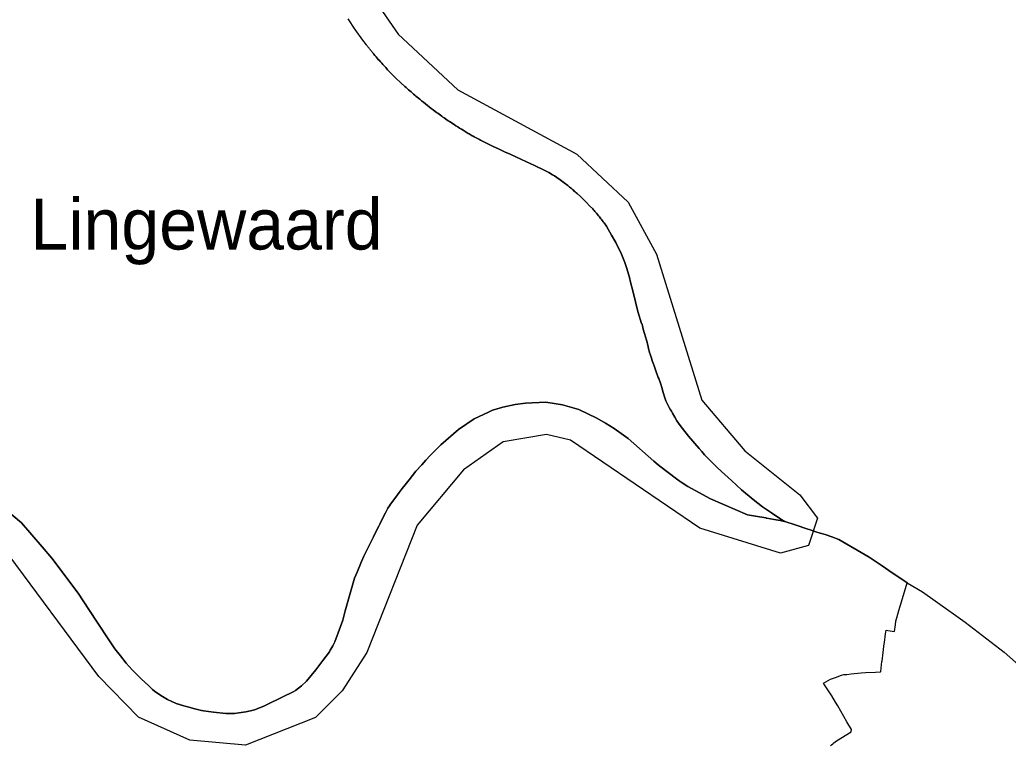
# Model space of a CAD drawing. Extents: x 113371 to 291721, y 393993 to 520143.
# Drawn here: x 192843 to 202548, y 429408 to 436525 of the extents above; entities that cross this region are included whole.
import ezdxf

# ---------------------------------------------------------------- set-up
doc = ezdxf.new("R2010")
doc.units = 0
for name, color, linetype in [('Boudingbox', 7, 'Continuous'), ('Default', 7, 'Continuous'), ('plaatsnamen', 7, 'Continuous'), ('vlieg gebied', 7, 'Continuous')]:
    doc.layers.add(name, color=color, linetype=linetype)

msp = doc.modelspace()

# ---------------------------------------------------------------- linework, layer by layer
at = {"layer": 'Boudingbox'}
msp.add_lwpolyline([(195676.083719, 437658.225888), (196556.945896, 436383.18747), (197142.997241, 435836.21838), (198310.654147, 435206.744651), (198814.741867, 434734.213382), (199092.660318, 434225.807727), (199540.546097, 432791.333676), (199962.119297, 432294.46026), (200501.752782, 431862.805644), (200676.148243, 431636.761083), (200585.491717, 431366.037395), (200310.139354, 431290.598699), (199520.441064, 431535.6128), (198250.155432, 432401.539517), (198015.469874, 432454.9006), (197590.459702, 432383.583408), (197198.077187, 432108.605271), (196744.145674, 431566.525607), (196251.335617, 430318.065969), (196009.740202, 429942.724312), (195746.220423, 429678.545334), (195058.112665, 429409.591246), (194512.13961, 429456.44294), (194007.836888, 429681.796786), (193619.497196, 430081.251608), (192673.95631, 431358.421884)], dxfattribs=at)
at = {"layer": 'Default'}
for points in [[(196426.065625, 436065.8025), (196416.625625, 436076.2125), (196407.225625, 436086.6725), (196396.055625, 436099.0625), (196384.925625, 436111.5125), (196373.855625, 436124.0025), (196362.845625, 436136.5325), (196351.875625, 436149.1225), (196342.455625, 436160.0125), (196340.965625, 436161.7425), (196330.095625, 436174.4125), (196319.285625, 436187.1325), (196314.195625, 436193.1725), (196311.805625, 436195.9325), (196308.695625, 436199.5325), (196303.245625, 436205.9325), (196297.855625, 436212.3925), (196292.525625, 436218.8925), (196287.255625, 436225.4425), (196282.035625, 436232.0325), (196276.885625, 436238.6725), (196271.785625, 436245.3625), (196266.745625, 436252.0925), (196261.765625, 436258.8625), (196256.845625, 436265.6825), (196251.985625, 436272.5425), (196247.175625, 436279.4425), (196212.255625, 436324.4525), (196136.355625, 436430.4725), (196067.825625, 436535.0125)], [(196310.250625, 436197.7325), (196311.805625, 436195.9325), (196314.195625, 436193.1725), (196319.285625, 436187.1325), (196330.095625, 436174.4125), (196340.965625, 436161.7425), (196342.455625, 436160.0125), (196351.875625, 436149.1225), (196362.845625, 436136.5325), (196373.855625, 436124.0025), (196384.925625, 436111.5125), (196396.055625, 436099.0625), (196407.225625, 436086.6725), (196416.625625, 436076.2125), (196426.065625, 436065.8025), (196435.565625, 436055.4425), (196445.115625, 436045.1325), (196454.725625, 436034.8625), (196464.385625, 436024.6525), (196474.095625, 436014.4825), (196483.855625, 436004.3725), (196493.665625, 435994.3025), (196503.535625, 435984.2925), (196513.445625, 435974.3225), (196535.915625, 435951.9225), (196584.575625, 435906.3825), (196624.255625, 435870.0525), (196636.105625, 435859.3525), (196648.015625, 435848.7025), (196659.965625, 435838.1125), (196671.955625, 435827.5725), (196683.995625, 435817.0825), (196696.085625, 435806.6525), (196708.225625, 435796.2725), (196720.405625, 435785.9525), (196732.635625, 435775.6825), (196744.905625, 435765.4725)], [(196985.115625, 435579.5425), (196972.175625, 435588.7325), (196959.285625, 435597.9725), (196946.435625, 435607.2725), (196933.625625, 435616.6325), (196920.865625, 435626.0425), (196901.805625, 435640.7425), (196882.785625, 435655.5025), (196863.805625, 435670.3125), (196844.875625, 435685.1825), (196825.995625, 435700.1025), (196807.145625, 435715.0825), (196788.345625, 435730.1125), (196769.595625, 435745.2025), (196757.225625, 435755.3125), (196744.905625, 435765.4725), (196732.635625, 435775.6825), (196720.405625, 435785.9525), (196708.225625, 435796.2725), (196696.085625, 435806.6525), (196683.995625, 435817.0825), (196671.955625, 435827.5725), (196659.965625, 435838.1125), (196648.015625, 435848.7025), (196636.105625, 435859.3525), (196624.255625, 435870.0525), (196584.575625, 435906.3825), (196535.915625, 435951.9225), (196513.445625, 435974.3225), (196503.535625, 435984.2925), (196493.665625, 435994.3025), (196483.855625, 436004.3725), (196474.095625, 436014.4825), (196464.385625, 436024.6525), (196454.725625, 436034.8625), (196445.115625, 436045.1325), (196435.565625, 436055.4425), (196426.065625, 436065.8025)], [(196744.905625, 435765.4725), (196757.225625, 435755.3125), (196769.595625, 435745.2025), (196788.345625, 435730.1125), (196807.145625, 435715.0825), (196825.995625, 435700.1025), (196844.875625, 435685.1825), (196863.805625, 435670.3125), (196882.785625, 435655.5025), (196901.805625, 435640.7425), (196920.865625, 435626.0425), (196933.625625, 435616.6325), (196946.435625, 435607.2725), (196959.285625, 435597.9725), (196972.175625, 435588.7325), (196985.115625, 435579.5425), (196998.085625, 435570.4125), (197011.095625, 435561.3425), (197024.155625, 435552.3325), (197037.245625, 435543.3825), (197050.375625, 435534.4825), (197063.555625, 435525.6425), (197076.765625, 435516.8625), (197090.015625, 435508.1425), (197107.645625, 435496.7625), (197125.305625, 435485.4325), (197143.005625, 435474.1625), (197160.735625, 435462.9325), (197178.505625, 435451.7725), (197196.305625, 435440.6525), (197205.985625, 435434.4725), (197215.695625, 435428.3625), (197225.445625, 435422.3025), (197235.235625, 435416.3125), (197245.065625, 435410.3825), (197254.935625, 435404.5125), (197264.835625, 435398.7125), (197274.775625, 435392.9725)], [(197542.795625, 435258.5125), (197491.265625, 435282.2325), (197431.245625, 435310.7425), (197418.465625, 435317.0025), (197405.715625, 435323.3225), (197392.985625, 435329.7125), (197380.295625, 435336.1625), (197367.635625, 435342.6625), (197355.005625, 435349.2325), (197342.415625, 435355.8725), (197329.845625, 435362.5625), (197317.315625, 435369.3125), (197304.815625, 435376.1325), (197294.765625, 435381.6725), (197284.755625, 435387.2925), (197274.775625, 435392.9725), (197264.835625, 435398.7125), (197254.935625, 435404.5125), (197245.065625, 435410.3825), (197235.235625, 435416.3125), (197225.445625, 435422.3025), (197215.695625, 435428.3625), (197205.985625, 435434.4725), (197196.305625, 435440.6525), (197178.505625, 435451.7725), (197160.735625, 435462.9325), (197143.005625, 435474.1625), (197125.305625, 435485.4325), (197107.645625, 435496.7625), (197090.015625, 435508.1425), (197076.765625, 435516.8625), (197063.555625, 435525.6425), (197050.375625, 435534.4825), (197037.245625, 435543.3825), (197024.155625, 435552.3325), (197011.095625, 435561.3425), (196998.085625, 435570.4125), (196985.115625, 435579.5425)], [(197274.775625, 435392.9725), (197284.755625, 435387.2925), (197294.765625, 435381.6725), (197304.815625, 435376.1325), (197317.315625, 435369.3125), (197329.845625, 435362.5625), (197342.415625, 435355.8725), (197355.005625, 435349.2325), (197367.635625, 435342.6625), (197380.295625, 435336.1625), (197392.985625, 435329.7125), (197405.715625, 435323.3225), (197418.465625, 435317.0025), (197431.245625, 435310.7425), (197491.265625, 435282.2325), (197542.795625, 435258.5125), (197603.035625, 435230.8625), (197656.285625, 435206.4325), (197769.925625, 435154.6425), (197895.025625, 435096.4125), (197997.345625, 435046.0025), (198036.205625, 435025.4625), (198071.645625, 435005.2225), (198091.895625, 434992.6425), (198116.605625, 434976.1725), (198148.315625, 434954.3125), (198187.315625, 434925.7225), (198222.735625, 434898.4925), (198240.785625, 434883.6625), (198258.755625, 434868.7225), (198268.355625, 434860.7125), (198277.915625, 434852.6425), (198287.415625, 434844.5125), (198296.865625, 434836.3125), (198306.255625, 434828.0625), (198315.605625, 434819.7525), (198347.735625, 434789.6225), (198378.535625, 434760.3225)], [(198556.565625, 434562.0625), (198548.915625, 434572.0925), (198541.215625, 434582.0825), (198533.455625, 434592.0225), (198525.635625, 434601.9125), (198518.585625, 434610.4225), (198511.485625, 434618.8825), (198504.335625, 434627.2925), (198497.125625, 434635.6625), (198489.865625, 434643.9925), (198482.555625, 434652.2725), (198475.195625, 434660.5125), (198467.785625, 434668.7025), (198437.875625, 434699.8425), (198407.985625, 434731.0225), (198378.535625, 434760.3225), (198347.735625, 434789.6225), (198315.605625, 434819.7525), (198306.255625, 434828.0625), (198296.865625, 434836.3125), (198287.415625, 434844.5125), (198277.915625, 434852.6425), (198268.355625, 434860.7125), (198258.755625, 434868.7225), (198240.785625, 434883.6625), (198222.735625, 434898.4925), (198187.315625, 434925.7225), (198148.315625, 434954.3125), (198116.605625, 434976.1725), (198091.895625, 434992.6425), (198071.645625, 435005.2225), (198036.205625, 435025.4625), (197997.345625, 435046.0025), (197895.025625, 435096.4125), (197769.925625, 435154.6425), (197656.285625, 435206.4325), (197603.035625, 435230.8625), (197542.795625, 435258.5125)], [(198378.535625, 434760.3225), (198407.985625, 434731.0225), (198437.875625, 434699.8425), (198467.785625, 434668.7025), (198475.195625, 434660.5125), (198482.555625, 434652.2725), (198489.865625, 434643.9925), (198497.125625, 434635.6625), (198504.335625, 434627.2925), (198511.485625, 434618.8825), (198518.585625, 434610.4225), (198525.635625, 434601.9125), (198533.455625, 434592.0225), (198541.215625, 434582.0825), (198548.915625, 434572.0925), (198556.565625, 434562.0625), (198564.155625, 434551.9925), (198571.685625, 434541.8825), (198579.155625, 434531.7225), (198602.045625, 434499.0225), (198622.665625, 434464.9325), (198636.925625, 434439.5025), (198653.615625, 434410.0625), (198693.805625, 434339.4625), (198750.605625, 434226.3925), (198784.135625, 434142.8025), (198802.545625, 434083.9025), (198829.065625, 433995.3025), (198840.145625, 433950.8625), (198860.555625, 433866.0325), (198886.745625, 433757.6525), (198910.025625, 433662.6925), (198948.535625, 433546.2725), (198948.755625, 433545.5825), (198951.965625, 433534.0825), (198955.945625, 433522.1525), (198962.895625, 433490.3625), (198976.805625, 433445.6625)], [(199084.605625, 433090.7625), (199071.015625, 433130.4325), (199061.465625, 433156.8825), (199053.305625, 433178.9925), (199047.425625, 433195.5225), (199040.815625, 433213.8925), (199034.575625, 433235.5625), (199026.855625, 433262.0125), (199022.445625, 433277.0725), (199020.535625, 433284.8625), (199013.565625, 433316.0825), (199008.785625, 433331.8825), (199006.585625, 433342.5325), (199001.435625, 433361.2725), (198996.675625, 433381.0925), (198976.805625, 433445.6625), (198962.895625, 433490.3625), (198955.945625, 433522.1525), (198951.965625, 433534.0825), (198948.755625, 433545.5825), (198948.535625, 433546.2725), (198910.025625, 433662.6925), (198886.745625, 433757.6525), (198860.555625, 433866.0325), (198840.145625, 433950.8625), (198829.065625, 433995.3025), (198802.545625, 434083.9025), (198784.135625, 434142.8025), (198750.605625, 434226.3925), (198693.805625, 434339.4625), (198653.615625, 434410.0625), (198636.925625, 434439.5025), (198622.665625, 434464.9325), (198602.045625, 434499.0225), (198579.155625, 434531.7225), (198571.685625, 434541.8825), (198564.155625, 434551.9925), (198556.565625, 434562.0625)], [(198976.805625, 433445.6625), (198996.675625, 433381.0925), (199001.435625, 433361.2725), (199006.585625, 433342.5325), (199008.785625, 433331.8825), (199013.565625, 433316.0825), (199020.535625, 433284.8625), (199022.445625, 433277.0725), (199026.855625, 433262.0125), (199034.575625, 433235.5625), (199040.815625, 433213.8925), (199047.425625, 433195.5225), (199053.305625, 433178.9925), (199061.465625, 433156.8825), (199071.015625, 433130.4325), (199084.605625, 433090.7625), (199112.155625, 433014.7225), (199115.905625, 433003.9925), (199138.305625, 432951.0925), (199147.195625, 432916.4925), (199160.055625, 432868.0025), (199177.105625, 432814.9625), (199186.655625, 432787.7725), (199194.735625, 432767.9425), (199202.815625, 432753.2425), (199219.715625, 432721.6525), (199232.205625, 432699.6125), (199241.015625, 432684.9225), (199252.035625, 432664.3525), (199274.075625, 432625.4125), (199295.385625, 432590.8825), (199327.635625, 432543.0925), (199349.335625, 432515.2725), (199408.585625, 432439.2925), (199513.835625, 432320.1125), (199537.875625, 432290.6725), (199564.285625, 432257.7525), (199575.425625, 432246.6225)], [(200362.955625, 431598.0725), (200364.035625, 431597.7425), (200364.625625, 431597.5625), (200315.665625, 431626.9325), (200224.285625, 431687.7525), (200134.285625, 431747.7525), (200044.285625, 431817.7525), (199928.455625, 431914.7625), (199829.525625, 432005.1825), (199731.385625, 432093.1125), (199688.095625, 432135.4125), (199670.175625, 432152.9225), (199657.685625, 432165.1325), (199624.285625, 432197.7525), (199594.755625, 432227.2925), (199575.425625, 432246.6225), (199564.285625, 432257.7525), (199537.875625, 432290.6725), (199513.835625, 432320.1125), (199408.585625, 432439.2925), (199349.335625, 432515.2725), (199327.635625, 432543.0925), (199295.385625, 432590.8825), (199274.075625, 432625.4125), (199252.035625, 432664.3525), (199241.015625, 432684.9225), (199232.205625, 432699.6125), (199219.715625, 432721.6525), (199202.815625, 432753.2425), (199194.735625, 432767.9425), (199186.655625, 432787.7725), (199177.105625, 432814.9625), (199160.055625, 432868.0025), (199147.195625, 432916.4925), (199138.305625, 432951.0925), (199115.905625, 433003.9925), (199112.155625, 433014.7225), (199084.605625, 433090.7625)], [(199625.165625, 431823.8925), (199402.485625, 431944.3425), (199337.425625, 431987.7925), (199316.065625, 432002.5025), (199181.195625, 432101.6225), (199111.895625, 432157.8825), (199068.725625, 432192.9325), (198814.545625, 432416.9725), (198679.375625, 432515.0725), (198592.715625, 432567.4725), (198509.035625, 432615.7025), (198332.335625, 432700.2425), (198171.945625, 432747.5925), (198006.335625, 432773.7625), (197806.515625, 432764.4125), (197706.135625, 432750.8025), (197584.515625, 432724.1025), (197497.525625, 432698.1925), (197485.725625, 432693.3125), (197443.855625, 432675.9825), (197303.195625, 432610.2825), (197149.575625, 432506.6325), (196976.905625, 432354.9125), (196959.475625, 432337.7625), (196927.095625, 432304.3925), (196876.155625, 432253.1225), (196828.935625, 432204.7525), (196789.385625, 432159.1225), (196732.915625, 432095.1425), (196664.765625, 432011.9125), (196652.635625, 431996.3625), (196625.645625, 431961.2025), (196597.585625, 431925.3825), (196568.145625, 431886.9025), (196550.365625, 431862.5125), (196515.395625, 431815.5725), (196483.395625, 431771.9125), (196472.605625, 431757.2025)], [(196876.155625, 432253.1225), (196927.095625, 432304.3925), (196959.475625, 432337.7625), (196976.905625, 432354.9125), (197149.575625, 432506.6325), (197303.195625, 432610.2825), (197443.855625, 432675.9825), (197485.725625, 432693.3125), (197497.525625, 432698.1925), (197584.515625, 432724.1025), (197706.135625, 432750.8025), (197806.515625, 432764.4125), (198006.335625, 432773.7625), (198171.945625, 432747.5925), (198332.335625, 432700.2425), (198509.035625, 432615.7025), (198592.715625, 432567.4725), (198679.375625, 432515.0725), (198814.545625, 432416.9725), (199068.725625, 432192.9325), (199111.895625, 432157.8825), (199181.195625, 432101.6225), (199316.065625, 432002.5025), (199337.425625, 431987.7925), (199402.485625, 431944.3425), (199625.165625, 431823.8925), (199746.425625, 431772.2425), (199987.065625, 431666.4425), (200046.945625, 431657.3125), (200087.395625, 431650.5025), (200148.075625, 431640.2825), (200166.975625, 431637.1025), (200169.875625, 431636.5825), (200170.115625, 431636.5425), (200178.375625, 431635.0725), (200248.155625, 431622.6925), (200308.385625, 431610.9125), (200362.955625, 431598.0725)], [(195817.425625, 430237.8025), (195883.065625, 430324.8525), (195890.975625, 430338.9325), (195897.425625, 430350.4025), (195915.305625, 430382.8725), (195934.995625, 430421.4225), (195936.355625, 430424.4225), (195947.195625, 430448.2525), (196013.705625, 430635.8025), (196038.775625, 430726.3625), (196129.135625, 431045.7225), (196155.935625, 431105.0725), (196191.945625, 431194.9525), (196198.815625, 431210.4225), (196222.125625, 431262.9025), (196247.685625, 431314.8625), (196270.775625, 431361.8625), (196293.865625, 431407.2225), (196315.305625, 431452.5725), (196336.755625, 431492.9825), (196368.085625, 431556.4825), (196377.155625, 431575.4525), (196405.195625, 431632.3525), (196434.055625, 431687.6025), (196457.255625, 431732.2925), (196472.605625, 431757.2025), (196483.395625, 431771.9125), (196515.395625, 431815.5725), (196550.365625, 431862.5125), (196568.145625, 431886.9025), (196597.585625, 431925.3825), (196625.645625, 431961.2025), (196652.635625, 431996.3625), (196664.765625, 432011.9125), (196732.915625, 432095.1425), (196789.385625, 432159.1225), (196828.935625, 432204.7525), (196876.155625, 432253.1225)], [(199575.425625, 432246.6225), (199594.755625, 432227.2925), (199624.285625, 432197.7525), (199657.685625, 432165.1325), (199670.175625, 432152.9225), (199688.095625, 432135.4125), (199731.385625, 432093.1125), (199829.525625, 432005.1825), (199928.455625, 431914.7625), (200044.285625, 431817.7525), (200134.285625, 431747.7525), (200224.285625, 431687.7525), (200315.665625, 431626.9325), (200364.625625, 431597.5625), (200444.555625, 431572.9425), (200455.965625, 431569.1325), (200495.165625, 431556.0725), (200539.495625, 431541.2925), (200558.845625, 431534.8425), (200612.865625, 431517.2925), (200659.275625, 431502.2425), (200700.895625, 431488.9725), (200749.615625, 431473.4325), (200814.325625, 431452.5125), (200883.755625, 431426.7325), (201182.555625, 431251.1925), (201308.305625, 431167.0725), (201376.525625, 431121.5025), (201554.855625, 431000.7825), (201704.555625, 430913.0625), (201977.685625, 430720.1425), (201987.015625, 430713.5425), (202124.485625, 430616.1625), (202506.785625, 430318.8625), (202785.545625, 430076.4225)], [(201432.205625, 430524.4525), (201440.505625, 430589.5525), (201440.555625, 430589.5425), (201444.835625, 430623.1125), (201449.905625, 430647.0825), (201452.595625, 430656.6225), (201472.625625, 430727.7925), (201498.465625, 430813.6625), (201554.855625, 431000.7825), (201376.525625, 431121.5025), (201308.305625, 431167.0725), (201182.555625, 431251.1925), (200883.755625, 431426.7325), (200814.325625, 431452.5125), (200749.615625, 431473.4325), (200700.895625, 431488.9725), (200659.275625, 431502.2425), (200612.865625, 431517.2925), (200558.845625, 431534.8425), (200539.495625, 431541.2925), (200495.165625, 431556.0725), (200455.965625, 431569.1325), (200444.555625, 431572.9425), (200364.625625, 431597.5625), (200364.035625, 431597.7425), (200362.955625, 431598.0725), (200308.385625, 431610.9125), (200248.155625, 431622.6925), (200178.375625, 431635.0725), (200170.115625, 431636.5425), (200169.875625, 431636.5825), (200166.975625, 431637.1025), (200148.075625, 431640.2825), (200087.395625, 431650.5025), (200046.945625, 431657.3125), (199987.065625, 431666.4425), (199746.425625, 431772.2425), (199625.165625, 431823.8925)], [(195063.895625, 429735.3425), (195038.415625, 429731.3525), (194993.925625, 429724.9025), (194949.905625, 429719.8925), (194918.725625, 429719.5325), (194867.205625, 429718.9425), (194746.225625, 429732.0425), (194696.815625, 429738.4025), (194647.395625, 429744.9725), (194628.075625, 429748.4725), (194560.795625, 429764.8625), (194501.195625, 429780.8425), (194453.105625, 429794.2325), (194379.035625, 429817.9225), (194291.865625, 429854.5625), (194229.135625, 429895.7325), (194164.715625, 429938.4425), (194145.415625, 429955.3625), (194110.035625, 429988.7525), (194034.705625, 430059.8525), (193946.535625, 430146.8325), (193887.265625, 430212.6125), (193830.435625, 430283.4425), (193776.625625, 430354.5425), (193717.765625, 430440.9825), (193610.335625, 430604.7025), (193522.385625, 430739.8625), (193416.535625, 430900.2325), (193156.455625, 431243.0925), (193062.705625, 431352.8525), (192859.705625, 431590.5225), (192696.495625, 431726.1425)], [(192696.495625, 431726.1425), (192859.705625, 431590.5225), (193062.705625, 431352.8525), (193156.455625, 431243.0925), (193416.535625, 430900.2325), (193522.385625, 430739.8625), (193610.335625, 430604.7025), (193717.765625, 430440.9825), (193776.625625, 430354.5425), (193830.435625, 430283.4425), (193887.265625, 430212.6125), (193946.535625, 430146.8325), (194034.705625, 430059.8525), (194110.035625, 429988.7525), (194145.415625, 429955.3625), (194164.715625, 429938.4425), (194229.135625, 429895.7325), (194291.865625, 429854.5625), (194379.035625, 429817.9225), (194453.105625, 429794.2325), (194501.195625, 429780.8425), (194560.795625, 429764.8625), (194628.075625, 429748.4725), (194647.395625, 429744.9725), (194696.815625, 429738.4025), (194746.225625, 429732.0425), (194867.205625, 429718.9425), (194918.725625, 429719.5325), (194949.905625, 429719.8925), (194993.925625, 429724.9025), (195038.415625, 429731.3525), (195063.895625, 429735.3425)], [(196472.605625, 431757.2025), (196457.255625, 431732.2925), (196434.055625, 431687.6025), (196405.195625, 431632.3525), (196377.155625, 431575.4525), (196368.085625, 431556.4825), (196336.755625, 431492.9825), (196315.305625, 431452.5725), (196293.865625, 431407.2225), (196270.775625, 431361.8625), (196247.685625, 431314.8625), (196222.125625, 431262.9025), (196198.815625, 431210.4225), (196191.945625, 431194.9525), (196155.935625, 431105.0725), (196129.135625, 431045.7225), (196038.775625, 430726.3625), (196013.705625, 430635.8025), (195947.195625, 430448.2525), (195936.355625, 430424.4225), (195934.995625, 430421.4225), (195915.305625, 430382.8725), (195897.425625, 430350.4025), (195890.975625, 430338.9325), (195883.065625, 430324.8525), (195817.425625, 430237.8025), (195748.075625, 430145.8425), (195657.125625, 430034.6525), (195609.135625, 429989.0025), (195551.555625, 429944.8025), (195527.805625, 429930.5825), (195424.535625, 429880.8025), (195406.465625, 429871.9325), (195277.825625, 429808.7925), (195239.305625, 429789.2425), (195148.455625, 429755.1125), (195106.875625, 429743.6925), (195063.895625, 429735.3425)], [(200802.975625, 429405.4925), (200811.685625, 429410.6625), (200824.175625, 429420.3025), (200836.645625, 429429.9225), (200862.065625, 429451.8025), (201004.785625, 429538.4925), (201008.725625, 429560.9125), (200962.085625, 429638.4425), (200873.105625, 429793.7325), (200851.515625, 429830.9725), (200814.325625, 429892.7825), (200769.575625, 429960.5225), (200748.915625, 429991.4625), (200733.115625, 430015.0325), (200733.015625, 430015.2125), (200802.565625, 430055.1825), (200852.295625, 430072.4425), (200910.275625, 430095.0625), (200934.215625, 430099.8325), (200961.475625, 430102.4325), (200961.595625, 430102.4425), (201005.755625, 430106.6325), (201105.055625, 430118.7025), (201145.805625, 430122.5725), (201245.205625, 430124.7225), (201295.025625, 430127.9025), (201295.425625, 430130.9225), (201307.775625, 430228.0625), (201308.355625, 430232.6025), (201318.985625, 430316.2725), (201330.445625, 430406.1425), (201331.305625, 430412.8225), (201331.745625, 430415.9425), (201344.005625, 430501.3525), (201346.425625, 430518.1725), (201348.995625, 430536.1025), (201364.955625, 430533.8725), (201432.205625, 430524.4525)], [(195063.895625, 429735.3425), (195106.875625, 429743.6925), (195148.455625, 429755.1125), (195239.305625, 429789.2425), (195277.825625, 429808.7925), (195406.465625, 429871.9325), (195424.535625, 429880.8025), (195527.805625, 429930.5825), (195551.555625, 429944.8025), (195609.135625, 429989.0025), (195657.125625, 430034.6525), (195748.075625, 430145.8425), (195817.425625, 430237.8025)]]:
    msp.add_lwpolyline(points, dxfattribs=at)
at = {"layer": 'vlieg gebied'}
msp.add_lwpolyline([(195676.083719, 437658.225888), (196556.945896, 436383.18747), (197142.997241, 435836.21838), (198310.654147, 435206.744651), (198814.741867, 434734.213382), (199092.660318, 434225.807727), (199540.546097, 432791.333676), (199962.119297, 432294.46026), (200501.752782, 431862.805644), (200676.148243, 431636.761083), (200585.491717, 431366.037395), (200310.139354, 431290.598699), (199520.441064, 431535.6128), (198250.155432, 432401.539517), (198015.469874, 432454.9006), (197590.459702, 432383.583408), (197198.077187, 432108.605271), (196744.145674, 431566.525607), (196251.335617, 430318.065969), (196009.740202, 429942.724312), (195746.220423, 429678.545334), (195058.112665, 429409.591246), (194512.13961, 429456.44294), (194007.836888, 429681.796786), (193619.497196, 430081.251608), (192673.95631, 431358.421884)], dxfattribs=at)

# ---------------------------------------------------------------- texts
at = {"layer": 'plaatsnamen'}
msp.add_text('Lingewaard', height=500, dxfattribs=at).set_placement((192947.888823, 434270.862254))

doc.saveas('drawing.dxf')
